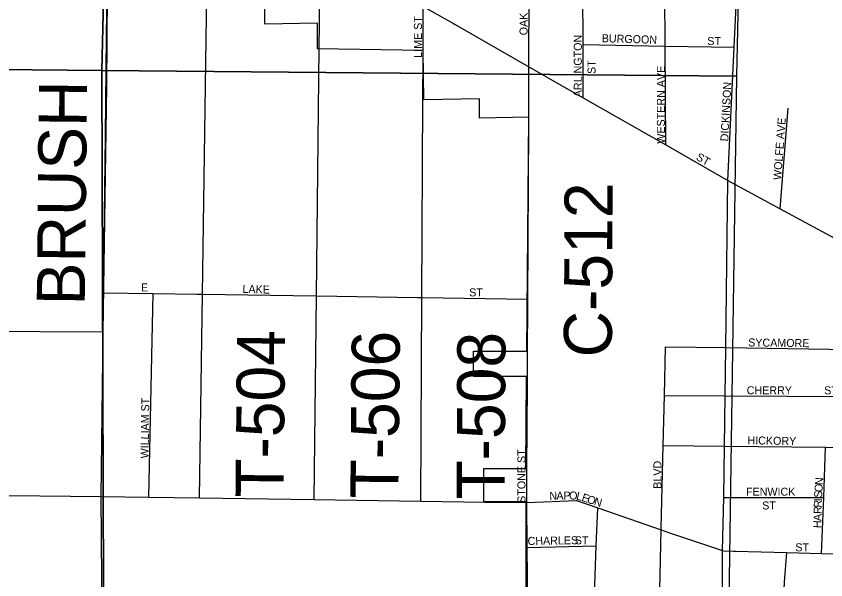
# Model space of a CAD drawing. Extents: x 1588073 to 2013523, y 1090242 to 1357120.
# Drawn here: x 1790397 to 1795455, y 1220221 to 1223743 of the extents above; entities that cross this region are included whole.
import ezdxf

# ---------------------------------------------------------------- set-up
doc = ezdxf.new("R2010")
doc.units = 0
for name, color, linetype in [('GM_X_City_Street', 7, 'Continuous'), ('GM_X_City_Street_Text', 7, 'Continuous'), ('GM_X_Corporation', 7, 'Continuous'), ('GM_X_County_Road', 7, 'Continuous'), ('GM_X_County_Road_Text', 7, 'Continuous'), ('GM_X_Section', 7, 'Continuous'), ('GM_X_Township_Road', 7, 'Continuous'), ('GM_X_Township_Road_Text', 7, 'Continuous'), ('GM_X_Township_Subdivision', 7, 'Continuous'), ('GM_X_Township_Subdivision_Text', 7, 'Continuous')]:
    doc.layers.add(name, color=color, linetype=linetype)

msp = doc.modelspace()

# ---------------------------------------------------------------- linework, layer by layer
at = {"layer": 'GM_X_City_Street'}
for points in [[(1794843.3, 1222716.9), (1794883.2, 1223548.4), (1794908.2, 1224068.8), (1794941, 1224749.8), (1794951.7, 1225096.8), (1794947.9, 1225368.8), (1794940.8, 1225879.2), (1794940.8, 1225879.4)], [(1793599.9, 1223427.5), (1793601.8, 1223907.4), (1793594.9, 1224789.2), (1793593.2, 1225287.8), (1793592.8, 1225355.8)], [(1790975.7, 1224926.6), (1790975.7, 1224926.6), (1791597.3, 1224571.5), (1792297, 1224171.8), (1792940.7, 1223804.1), (1793129.1, 1223696.5)], [(1792291.7, 1223701.5), (1792291.7, 1223701.5), (1792297, 1224171.8)], [(1794456, 1222938.3), (1794451.1, 1223556.1), (1794448.5, 1223890.5), (1794447.1, 1224073.2)], [(1793939.7, 1223233.3), (1793938.7, 1223565.3), (1793937.6, 1223900.7)], [(1792939.2, 1223484.3), (1792940.7, 1223804.1)], [(1793129.1, 1223696.5), (1793139.5, 1223690.5), (1793599.9, 1223427.5)], [(1793938.7, 1223565.3), (1794451.1, 1223556.1), (1794883.2, 1223548.4)], [(1793599.5, 1223064.5), (1793600.6, 1223269.7), (1793599.9, 1223427.5)], [(1793599.9, 1223427.5), (1793939.7, 1223233.3), (1794456, 1222938.3), (1794843.3, 1222716.9), (1795170.7, 1222539.9), (1795536.3, 1222342.3), (1795797.3, 1222201.2), (1795860.9, 1222166.7), (1796185.5, 1221991.3), (1796606.7, 1221763.5), (1796705.2, 1221682.4), (1797347.9, 1221341.7), (1797708, 1221150.7), (1798014.6, 1220977), (1798386.6, 1220766.2), (1798658.3, 1220612.2), (1798658.3, 1220612.2)], [(1795170.7, 1222539.9), (1795219.3, 1223168.3)], [(1794810.2, 1220339), (1794810.6, 1220404.9), (1794818.9, 1220735.6), (1794822.8, 1221056.4), (1794826.7, 1221370.9), (1794830.4, 1221671.8), (1794843.3, 1222716.9)], [(1794427, 1220535.7), (1794427.1, 1220542.1), (1794439.2, 1221060.6), (1794446.5, 1221372.9), (1794453.6, 1221677.3)], [(1794453.6, 1221677.3), (1794830.4, 1221671.8), (1795475, 1221662.4), (1795990.5, 1221654.8), (1796261.7, 1221650.9), (1796261.7, 1221650.9)], [(1793591, 1221445.4), (1793591.8, 1221593.8), (1793591.8, 1221604.4)], [(1794446.5, 1221372.9), (1794826.7, 1221370.9), (1795989.6, 1221365.1), (1796552.3, 1221362.3)], [(1794439.2, 1221060.6), (1794822.8, 1221056.4), (1795453.2, 1221049.3), (1795699.9, 1221046.5), (1795988.7, 1221043.3), (1796401.2, 1221038.6), (1796808.2, 1221034.1), (1796985.5, 1221032.1), (1797162.7, 1221030.1)], [(1795428.6, 1220385.8), (1795441.6, 1220736.2), (1795453.2, 1221049.3)], [(1793587.1, 1220703.6), (1793588.2, 1220913), (1793588.2, 1220915.5)], [(1793587.1, 1220703.6), (1793896.9, 1220716.2), (1794030.2, 1220670.2), (1794426.9, 1220533.3), (1794472.6, 1220517.5), (1794810.6, 1220404.9), (1794818, 1220402.4), (1794877.3, 1220400.8), (1794891.1, 1220400.5)], [(1794818.9, 1220735.6), (1795441.6, 1220736.2)], [(1793962, 1218887.7), (1793991.3, 1219655.3), (1794006.9, 1220063.7), (1794021.1, 1220432.6), (1794030.2, 1220670.2)], [(1794393.5, 1219097.2), (1794406.4, 1219653.6), (1794416, 1220064.2), (1794426.9, 1220533.3), (1794427, 1220535.7)], [(1793590.1, 1220424.1), (1794021.1, 1220432.6)], [(1794891.1, 1220400.5), (1795210.5, 1220391.8), (1795428.6, 1220385.8), (1795579.4, 1220381.7), (1795727.5, 1220377.7), (1796246.9, 1220363.6)], [(1795199.8, 1220232.9), (1795210.5, 1220391.8)], [(1794786.2, 1218082.7), (1794786.2, 1218082.7), (1794790.7, 1218452.5), (1794796, 1218877.3), (1794800.2, 1219222.1), (1794805.5, 1219651.9), (1794810.2, 1220339)], [(1795160.8, 1219650.5), (1795199.8, 1220232.9), (1795199.8, 1220232.9)]]:
    msp.add_lwpolyline(points, dxfattribs=at)
at = {"layer": 'GM_X_Corporation'}
for points in [[(1790970.7, 1224467), (1790962, 1223305.9), (1790938, 1221768.4), (1790146.7, 1221772.1)], [(1793588, 1218087.3), (1793583.7, 1220709), (1793318.3, 1220708.5), (1793317.9, 1220917), (1793582, 1220917.5), (1793584.5, 1221491.1), (1793254.8, 1221491), (1793254.8, 1221649.4), (1793586.3, 1221649.5), (1793599.2, 1223111.5), (1793291.5, 1223106.1), (1793291.5, 1223227.2), (1792944.4, 1223221), (1792938.9, 1223528.2), (1792280.6, 1223539.5), (1792280.6, 1223699.6), (1791950.4, 1223693.7), (1791950.4, 1223845.6)]]:
    msp.add_lwpolyline(points, dxfattribs=at)
at = {"layer": 'GM_X_County_Road'}
for points in [[(1790958.9, 1223418.4), (1790971, 1224508.2), (1790971.1, 1224510.5)], [(1790954.3, 1223002.4), (1790958.8, 1223409.9), (1790958.9, 1223418.4)], [(1793591.8, 1221604.4), (1793593, 1221975.3), (1793599.5, 1223060), (1793599.5, 1223064.5)], [(1790943.3, 1222014.3), (1790954.2, 1222991.5), (1790954.3, 1223002.4)], [(1790941.5, 1221855.3), (1790943.3, 1222014.3)], [(1790929.2, 1220742.7), (1790940.6, 1221768.4), (1790941.5, 1221855.3)], [(1793588.2, 1220915.5), (1793590.9, 1221436.7), (1793591, 1221445.4)], [(1790160.8, 1220750.5), (1790929.2, 1220742.7)], [(1790929.2, 1220742.7), (1791225.8, 1220738.3), (1791542.5, 1220733.6), (1792258.1, 1220723.1), (1792925.6, 1220713.3), (1793326.5, 1220707.4), (1793326.5, 1220707.4)], [(1790949.8, 1218107.6), (1790943.6, 1218895.2), (1790937.3, 1219705.9), (1790929.2, 1220742.7)], [(1793326.5, 1220707.4), (1793587.1, 1220703.6)], [(1793600.8, 1218103.6), (1793607.1, 1218878.2), (1793598.5, 1219656.8), (1793594.1, 1220063.2), (1793590.1, 1220424.1), (1793587.1, 1220703.6)]]:
    msp.add_lwpolyline(points, dxfattribs=at)
at = {"layer": 'GM_X_Section'}
for points in [[(1785731.5, 1228782.2), (1791058, 1228706), (1790931.8, 1223403.9), (1785709.2, 1223453.4)], [(1791058, 1228706), (1796314.5, 1228634.1), (1796297.6, 1225086.2), (1794935, 1225106.5), (1794897.8, 1223367.8), (1790931.8, 1223403.9)], [(1785709.2, 1223453.4), (1790931.8, 1223403.9), (1790948.4, 1218200.8), (1790239.7, 1218156.2), (1785663.5, 1218206.9)], [(1790931.8, 1223403.9), (1794897.8, 1223367.8), (1794819.6, 1218086.9), (1790948.4, 1218200.8)]]:
    msp.add_lwpolyline(points, close=True, dxfattribs=at)
at = {"layer": 'GM_X_Township_Road'}
for points in [[(1791542.5, 1220733.6), (1791560.7, 1222005.2), (1791587.5, 1223888)], [(1792289.9, 1223544.8), (1792289.9, 1223544.8), (1792291.7, 1223701.5)], [(1792258.1, 1220723.1), (1792272.4, 1221994.7), (1792289.9, 1223544.8)], [(1792937.9, 1223217.9), (1792939.2, 1223484.3), (1792939.2, 1223484.3)], [(1792925.6, 1220713.3), (1792931.8, 1221985), (1792937.9, 1223217.9), (1792937.9, 1223217.9)]]:
    msp.add_lwpolyline(points, dxfattribs=at)
at = {"layer": 'GM_X_Township_Subdivision'}
for points in [[(1790943.3, 1222014.3), (1791253, 1222009.7), (1791526.2, 1222005.7)], [(1791225.8, 1220738.3), (1791253, 1222009.7)], [(1791526.2, 1222005.7), (1791560.7, 1222005.2), (1792268.2, 1221994.8)], [(1792268.2, 1221994.8), (1792272.4, 1221994.7), (1792904.1, 1221985.4)], [(1792904.1, 1221985.4), (1792931.8, 1221985), (1793593, 1221975.3)]]:
    msp.add_lwpolyline(points, dxfattribs=at)

# ---------------------------------------------------------------- texts
at = {"layer": 'GM_X_City_Street_Text'}
for s, rotation, p in [('LIME ST', 90, (1792931.8, 1223483)), ('OAK', 90, (1793591.8, 1223623.8)), ('ARLINGTON', 90, (1793930.6, 1223236.6)), ('BURGOON', 358.3391, (1794054.7, 1223580.4)), ('ST', 0, (1794714.4, 1223562.8)), ('ST', 90, (1794016.6, 1223381.8)), ('WESTERN AVE', 90, (1794449.8, 1222946.2)), ('DICKINSON', 86.986, (1794845.8, 1222959.9)), ('WOLFE AVE', 85.7105, (1795175.9, 1222718.1)), ('ST', 330.2568, (1794639.9, 1222848.8)), ('SYCAMORE', 359.2549, (1794969.8, 1221679.6)), ('CHERRY', 0, (1794960.8, 1221380.4)), ('ST', 0, (1795444.8, 1221380.4)), ('HICKORY', 359.0894, (1794965.4, 1221068)), ('STONE ST', 90, (1793578.6, 1220702.2)), ('BLVD', 90, (1794427.9, 1220790.2)), ('N', 85.7781, (1795436.5, 1220811.5)), ('O', 85.7999, (1795433.3, 1220767.7)), ('N', 1.3442, (1793728.6, 1220720.4)), ('A', 1.3503, (1793772.6, 1220721.4)), ('P', 1.3386, (1793816.6, 1220722.5)), ('O', 359.2022, (1793851.3, 1220723.3)), ('L', 346.7258, (1793892.4, 1220723)), ('E', 342.0706, (1793925.6, 1220715.2)), ('FENWICK', 0, (1794956.4, 1220746.8)), ('S', 86.583, (1795431.2, 1220732.7)), ('O', 341.8311, (1793959.1, 1220704.4)), ('N', 343.8455, (1794002.7, 1220690.1)), ('ST', 0, (1795057.6, 1220660.8)), ('R', 88.6872, (1795429.6, 1220671.6)), ('I', 88.0763, (1795430.5, 1220711)), ('R', 88.6641, (1795428.6, 1220632)), ('A', 88.6867, (1795427.6, 1220588)), ('H', 88.6665, (1795426.6, 1220544)), ('CHARLES', 0.9106, (1793592.3, 1220438.8)), ('ST', 0, (1793887.2, 1220443.2)), ('ST', 0, (1795264.4, 1220399.2))]:
    msp.add_text(s, height=50, rotation=rotation, dxfattribs=at).set_placement(p)
at = {"layer": 'GM_X_County_Road_Text'}
for s, rotation, p in [('BRUSH', 89.3844, (1790825.5, 1221935)), ('C-512', 89.7247, (1794118.1, 1221610.5))]:
    msp.add_text(s, height=300, rotation=rotation, dxfattribs=at).set_placement(p)
at = {"layer": 'GM_X_Township_Road_Text'}
for s, rotation, p in [('T-504', 89.4386, (1792067.1, 1220732.3)), ('T-506', 89.4386, (1792784.3, 1220727.9)), ('T-508', 89.7193, (1793448.7, 1220721.7))]:
    msp.add_text(s, height=300, rotation=rotation, dxfattribs=at).set_placement(p)
at = {"layer": 'GM_X_Township_Subdivision_Text'}
for s, rotation, p in [('E', 0, (1791176.8, 1222022.8)), ('LAKE', 358.4526, (1791810.7, 1222014)), ('ST', 0, (1793227.2, 1221992)), ('WILLIAM ST', 89.2931, (1791224.6, 1220979.5))]:
    msp.add_text(s, height=50, rotation=rotation, dxfattribs=at).set_placement(p)

doc.saveas('drawing.dxf')
